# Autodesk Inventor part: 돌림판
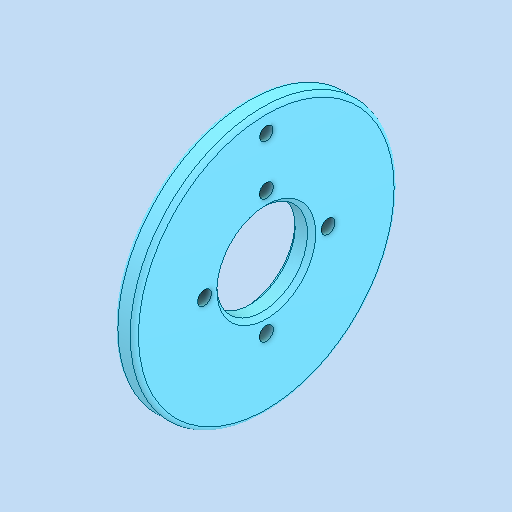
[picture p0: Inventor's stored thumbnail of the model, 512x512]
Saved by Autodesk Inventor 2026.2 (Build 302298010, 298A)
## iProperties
Created: 2026-08
Part Number: 돌림판
Material: 강철, 연강
Document SubType Name: Modeling
Designer: PC-2-06
Density: 7.85 g/cm^3
Appearance: 기본값
Author: jhkim
Sending System: Autodesk Inventor 2027
Preprocessor: ST-DEVELOPER v20.1
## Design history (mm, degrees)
feature "솔리드1"
node "솔리드2"
